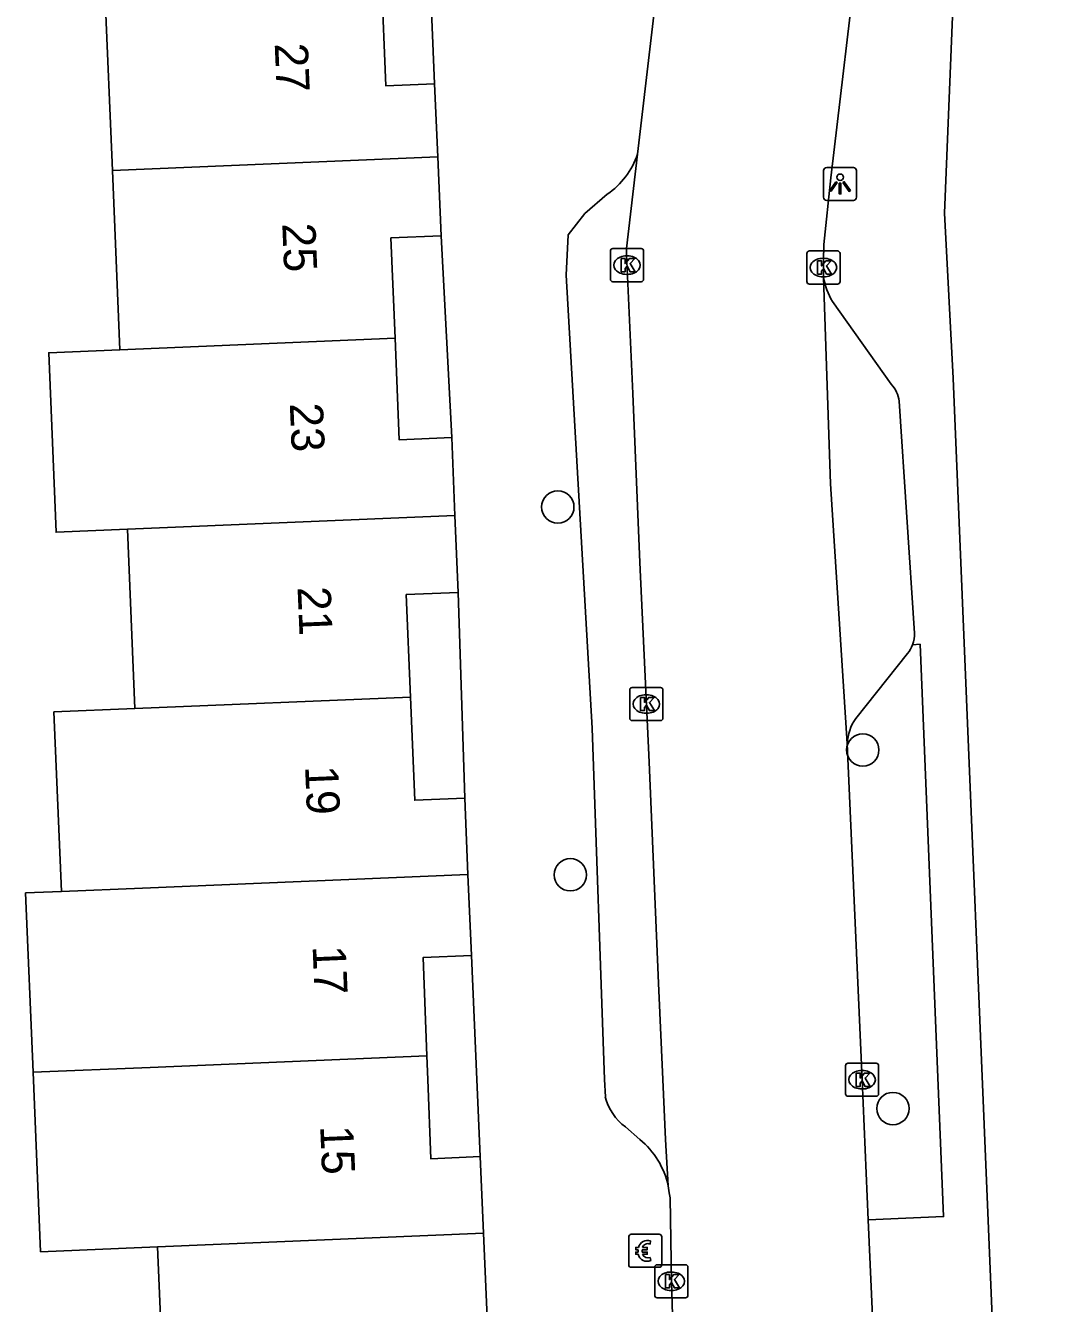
# Model space of a CAD drawing. Extents: x 161243 to 161752, y 384138 to 384885.
# Drawn here: x 161353.86 to 161384.53, y 384243.24 to 384281.86 of the extents above; entities that cross this region are included whole.
import ezdxf

# ---------------------------------------------------------------- set-up
doc = ezdxf.new("R2010")
doc.units = 0
for name, color, linetype in [('IMGEO_Betaalautomaat', 7, 'Continuous'), ('IMGEO_Boom', 7, 'Continuous'), ('IMGEO_Kolk', 7, 'Continuous'), ('IMGEO_Lichtpunt', 7, 'Continuous'), ('IMGEO_Pand', 7, 'Continuous'), ('IMGEO_Pand_nummerreeks', 7, 'Continuous'), ('IMGEO_Parkeervlak_open', 7, 'Continuous'), ('IMGEO_Rijbaan_lokaal_open', 7, 'Continuous'), ('IMGEO_Voetpad_open', 7, 'Continuous')]:
    doc.layers.add(name, color=color, linetype=linetype)

msp = doc.modelspace()

# ---------------------------------------------------------------- linework, layer by layer
at = {"layer": 'IMGEO_Betaalautomaat'}
for p, q in [((161372.086, 384244.402), (161372.086, 384245.243)), ((161372.086, 384245.243), (161372.086, 384244.402)), ((161372.161, 384245.326), (161373.002, 384245.326)), ((161373.002, 384245.326), (161372.161, 384245.326)), ((161372.748, 384245.131), (161372.731, 384245.031)), ((161373.085, 384245.252), (161373.085, 384244.411)), ((161373.085, 384244.411), (161373.085, 384245.252)), ((161372.369, 384244.79), (161372.369, 384244.858)), ((161372.49, 384244.858), (161372.49, 384244.79)), ((161372.735, 384244.625), (161372.757, 384244.538)), ((161373.011, 384244.327), (161372.17, 384244.327)), ((161372.17, 384244.327), (161373.011, 384244.327))]:
    msp.add_line(p, q, dxfattribs=at)
for points in [[(161372.369, 384244.858), (161372.3, 384244.858), (161372.3, 384244.927), (161372.379, 384244.927)], [(161372.374, 384244.721), (161372.3, 384244.721), (161372.3, 384244.79), (161372.369, 384244.79)], [(161372.501, 384244.927), (161372.648, 384244.927), (161372.648, 384244.858), (161372.49, 384244.858)], [(161372.49, 384244.79), (161372.648, 384244.79), (161372.648, 384244.721), (161372.504, 384244.721)]]:
    msp.add_lwpolyline(points, dxfattribs=at)
for centre, radius, start, end in [((161372.164, 384245.249), 0.0779, 92.4484, 184.2845), ((161372.164, 384245.249), 0.0779, 92.4484, 184.2845), ((161372.662, 384244.851), 0.293, 73.014, 165.0139), ((161372.668, 384244.864), 0.179, 69.3236, 159.5683), ((161373.008, 384245.249), 0.0779, 2.4484, 94.2845), ((161373.008, 384245.249), 0.0779, 2.4484, 94.2845), ((161372.635, 384244.776), 0.267, 191.8096, 297.0389), ((161372.668, 384244.791), 0.179, 202.7625, 291.8693), ((161372.164, 384244.405), 0.0779, 182.4484, 274.2845), ((161372.164, 384244.405), 0.0779, 182.4484, 274.2845), ((161373.008, 384244.405), 0.0779, 272.4484, 4.2845), ((161373.008, 384244.405), 0.0779, 272.4484, 4.2845)]:
    msp.add_arc(centre, radius, start, end, dxfattribs=at)
at = {"layer": 'IMGEO_Boom'}
for centre in [(161369.944, 384267.31), (161379.159, 384259.965), (161370.322, 384256.192), (161380.07, 384249.126)]:
    msp.add_circle(centre, 0.489, dxfattribs=at)
at = {"layer": 'IMGEO_Kolk'}
for p, q in [((161371.609, 384275.121), (161372.461, 384275.121)), ((161371.534, 384274.195), (161371.534, 384275.047)), ((161372.022, 384274.901), (161372.047, 384274.901)), ((161372.535, 384275.047), (161372.535, 384274.195)), ((161377.47, 384274.122), (161377.47, 384274.974)), ((161377.545, 384275.048), (161378.397, 384275.048)), ((161377.958, 384274.828), (161377.983, 384274.828)), ((161378.471, 384274.974), (161378.471, 384274.122)), ((161372.045, 384274.341), (161372.02, 384274.341)), ((161372.461, 384274.121), (161371.609, 384274.121)), ((161378.397, 384274.048), (161377.545, 384274.048)), ((161377.981, 384274.268), (161377.956, 384274.268)), ((161372.118, 384260.928), (161372.118, 384261.78)), ((161372.193, 384261.854), (161373.045, 384261.854)), ((161372.606, 384261.634), (161372.631, 384261.634)), ((161373.119, 384261.78), (161373.119, 384260.928)), ((161373.045, 384260.854), (161372.193, 384260.854)), ((161372.629, 384261.074), (161372.604, 384261.074)), ((161378.636, 384249.572), (161378.636, 384250.424)), ((161378.711, 384250.498), (161379.563, 384250.498)), ((161379.637, 384250.424), (161379.637, 384249.572)), ((161379.124, 384250.278), (161379.149, 384250.278)), ((161379.147, 384249.718), (161379.122, 384249.718)), ((161379.563, 384249.498), (161378.711, 384249.498)), ((161372.873, 384243.48), (161372.873, 384244.332)), ((161372.948, 384244.406), (161373.8, 384244.406)), ((161373.361, 384244.186), (161373.386, 384244.186)), ((161373.874, 384244.332), (161373.874, 384243.48)), ((161373.8, 384243.406), (161372.948, 384243.406)), ((161373.384, 384243.626), (161373.359, 384243.626))]:
    msp.add_line(p, q, dxfattribs=at)
for points in [[(161371.609, 384275.121), (161372.461, 384275.121)], [(161371.534, 384274.195), (161371.534, 384275.047)], [(161371.855, 384274.821), (161371.978, 384274.821), (161371.978, 384274.67), (161372.108, 384274.821), (161372.272, 384274.821), (161372.126, 384274.67), (161372.279, 384274.421), (161372.127, 384274.421), (161372.042, 384274.585), (161371.978, 384274.518), (161371.978, 384274.421), (161371.855, 384274.421), (161371.855, 384274.821)], [(161372.535, 384275.047), (161372.535, 384274.195)], [(161377.47, 384274.122), (161377.47, 384274.974)], [(161377.545, 384275.048), (161378.397, 384275.048)], [(161377.791, 384274.748), (161377.914, 384274.748), (161377.914, 384274.597), (161378.044, 384274.748), (161378.208, 384274.748), (161378.062, 384274.597), (161378.215, 384274.348), (161378.063, 384274.348), (161377.978, 384274.512), (161377.914, 384274.445), (161377.914, 384274.348), (161377.791, 384274.348), (161377.791, 384274.748)], [(161378.471, 384274.974), (161378.471, 384274.122)], [(161372.461, 384274.121), (161371.609, 384274.121)], [(161378.397, 384274.048), (161377.545, 384274.048)], [(161372.118, 384260.928), (161372.118, 384261.78)], [(161372.193, 384261.854), (161373.045, 384261.854)], [(161373.119, 384261.78), (161373.119, 384260.928)], [(161372.439, 384261.554), (161372.562, 384261.554), (161372.562, 384261.403), (161372.692, 384261.554), (161372.856, 384261.554), (161372.71, 384261.403), (161372.863, 384261.154), (161372.711, 384261.154), (161372.626, 384261.318), (161372.562, 384261.251), (161372.562, 384261.154), (161372.439, 384261.154), (161372.439, 384261.554)], [(161373.045, 384260.854), (161372.193, 384260.854)], [(161378.636, 384249.572), (161378.636, 384250.424)], [(161378.711, 384250.498), (161379.563, 384250.498)], [(161379.637, 384250.424), (161379.637, 384249.572)], [(161378.957, 384250.198), (161379.08, 384250.198), (161379.08, 384250.047), (161379.21, 384250.198), (161379.374, 384250.198), (161379.228, 384250.047), (161379.381, 384249.798), (161379.229, 384249.798), (161379.144, 384249.962), (161379.08, 384249.895), (161379.08, 384249.798), (161378.957, 384249.798), (161378.957, 384250.198)], [(161379.563, 384249.498), (161378.711, 384249.498)], [(161372.873, 384243.48), (161372.873, 384244.332)], [(161372.948, 384244.406), (161373.8, 384244.406)], [(161373.874, 384244.332), (161373.874, 384243.48)], [(161373.194, 384244.106), (161373.317, 384244.106), (161373.317, 384243.955), (161373.447, 384244.106), (161373.611, 384244.106), (161373.465, 384243.955), (161373.618, 384243.706), (161373.466, 384243.706), (161373.381, 384243.87), (161373.317, 384243.803), (161373.317, 384243.706), (161373.194, 384243.706), (161373.194, 384244.106)], [(161373.8, 384243.406), (161372.948, 384243.406)]]:
    msp.add_lwpolyline(points, dxfattribs=at)
for centre, start, end in [((161371.611, 384275.045), 91.552, 178.448), ((161371.611, 384275.045), 91.552, 178.448), ((161372.459, 384275.045), 1.552, 88.448), ((161372.459, 384275.045), 1.552, 88.448), ((161377.547, 384274.972), 91.552, 178.448), ((161377.547, 384274.972), 91.552, 178.448), ((161378.395, 384274.972), 1.552, 88.448), ((161378.395, 384274.972), 1.552, 88.448), ((161371.611, 384274.197), 181.552, 268.448), ((161371.611, 384274.197), 181.552, 268.448), ((161372.459, 384274.197), 271.552, 358.448), ((161372.459, 384274.197), 271.552, 358.448), ((161377.547, 384274.124), 181.552, 268.448), ((161377.547, 384274.124), 181.552, 268.448), ((161378.395, 384274.124), 271.552, 358.448), ((161378.395, 384274.124), 271.552, 358.448), ((161372.195, 384261.778), 91.552, 178.448), ((161372.195, 384261.778), 91.552, 178.448), ((161373.043, 384261.778), 1.552, 88.448), ((161373.043, 384261.778), 1.552, 88.448), ((161372.195, 384260.93), 181.552, 268.448), ((161372.195, 384260.93), 181.552, 268.448), ((161373.043, 384260.93), 271.552, 358.448), ((161373.043, 384260.93), 271.552, 358.448), ((161378.713, 384250.422), 91.552, 178.448), ((161378.713, 384250.422), 91.552, 178.448), ((161379.561, 384250.422), 1.552, 88.448), ((161379.561, 384250.422), 1.552, 88.448), ((161378.713, 384249.574), 181.552, 268.448), ((161378.713, 384249.574), 181.552, 268.448), ((161379.561, 384249.574), 271.552, 358.448), ((161379.561, 384249.574), 271.552, 358.448), ((161372.95, 384244.33), 91.552, 178.448), ((161372.95, 384244.33), 91.552, 178.448), ((161373.798, 384244.33), 1.552, 88.448), ((161373.798, 384244.33), 1.552, 88.448), ((161372.95, 384243.482), 181.552, 268.448), ((161372.95, 384243.482), 181.552, 268.448), ((161373.798, 384243.482), 271.552, 358.448), ((161373.798, 384243.482), 271.552, 358.448)]:
    msp.add_arc(centre, 0.0765, start, end, dxfattribs=at)
for centre, major_axis, ratio, start_param, end_param in [((161372.021, 384274.621), (-0.387, 0.002), 0.722429, 4.712389, 7.853982), ((161372.046, 384274.621), (-0.39, 0.002), 0.717154, 1.570796, 4.712389), ((161377.957, 384274.548), (-0.387, 0.002), 0.722429, 4.712389, 7.853982), ((161377.982, 384274.548), (-0.39, 0.002), 0.717154, 1.570796, 4.712389), ((161372.605, 384261.354), (-0.387, 0.002), 0.722429, 4.712389, 7.853982), ((161372.63, 384261.354), (-0.39, 0.002), 0.717154, 1.570796, 4.712389), ((161379.123, 384249.998), (-0.387, 0.002), 0.722429, 4.712389, 7.853982), ((161379.148, 384249.998), (-0.39, 0.002), 0.717154, 1.570796, 4.712389), ((161373.36, 384243.906), (-0.387, 0.002), 0.722429, 4.712389, 7.853982), ((161373.385, 384243.906), (-0.39, 0.002), 0.717154, 1.570796, 4.712389)]:
    msp.add_ellipse(centre, major_axis=major_axis, ratio=ratio, start_param=start_param, end_param=end_param, dxfattribs=at)
at = {"layer": 'IMGEO_Lichtpunt'}
for p, q in [((161377.974, 384277.478), (161377.974, 384276.671)), ((161377.974, 384277.478), (161377.974, 384276.671)), ((161378.876, 384277.573), (161378.068, 384277.573)), ((161378.876, 384277.573), (161378.068, 384277.573)), ((161378.97, 384276.671), (161378.97, 384277.478)), ((161378.97, 384276.671), (161378.97, 384277.478)), ((161378.068, 384276.577), (161378.876, 384276.577)), ((161378.068, 384276.577), (161378.876, 384276.577))]:
    msp.add_line(p, q, dxfattribs=at)
for points in [[(161378.348, 384277.142), (161378.387, 384277.114), (161378.199, 384276.852), (161378.161, 384276.879), (161378.348, 384277.142)], [(161378.45, 384277.094), (161378.497, 384277.094), (161378.497, 384276.772), (161378.45, 384276.772), (161378.45, 384277.094)], [(161378.56, 384277.114), (161378.598, 384277.141), (161378.785, 384276.879), (161378.746, 384276.851), (161378.56, 384277.114)]]:
    msp.add_lwpolyline(points, dxfattribs=at)
msp.add_circle((161378.473, 384277.276), 0.0994, dxfattribs=at)
for centre, start, end in [((161378.068, 384277.478), 90, 180), ((161378.068, 384277.478), 90, 180), ((161378.876, 384277.478), 0, 90), ((161378.876, 384277.478), 0, 90), ((161378.068, 384276.671), 180, 270), ((161378.068, 384276.671), 180, 270), ((161378.876, 384276.671), 270, 0), ((161378.876, 384276.671), 270, 360)]:
    msp.add_arc(centre, 0.0946, start, end, dxfattribs=at)
at = {"layer": 'IMGEO_Pand'}
for points in [[(161366.223, 384280.106), (161364.747, 384280.045), (161364.613, 384283.257)], [(161356.488, 384277.486), (161356.262, 384282.909)], [(161366.223, 384280.106), (161366.315, 384277.896)], [(161356.488, 384277.486), (161366.315, 384277.896)], [(161366.315, 384277.896), (161366.415, 384275.508)], [(161356.715, 384272.063), (161356.488, 384277.486)], [(161365.026, 384272.41), (161364.9, 384275.445), (161366.415, 384275.508)], [(161365.026, 384272.41), (161356.715, 384272.063)], [(161366.737, 384269.406), (161365.154, 384269.34), (161365.026, 384272.41)], [(161356.942, 384266.639), (161354.786, 384266.549), (161354.56, 384271.973), (161356.715, 384272.063)], [(161366.737, 384269.406), (161366.835, 384267.052)], [(161356.942, 384266.639), (161366.835, 384267.052)], [(161366.835, 384267.052), (161366.932, 384264.726)], [(161357.168, 384261.216), (161356.942, 384266.639)], [(161365.492, 384261.563), (161365.363, 384264.66), (161366.932, 384264.726)], [(161365.492, 384261.563), (161357.168, 384261.216)], [(161367.134, 384258.507), (161365.622, 384258.444), (161365.492, 384261.563)], [(161354.946, 384255.691), (161354.72, 384261.114), (161357.168, 384261.216)], [(161367.134, 384258.507), (161367.23, 384256.203)], [(161367.23, 384256.203), (161357.395, 384255.793), (161354.946, 384255.691)], [(161367.23, 384256.203), (161367.332, 384253.749)], [(161354.089, 384250.222), (161353.862, 384255.646), (161354.946, 384255.691)], [(161365.989, 384250.718), (161365.875, 384253.688), (161367.332, 384253.749)], [(161354.089, 384250.222), (161357.622, 384250.369), (161365.989, 384250.718)], [(161367.599, 384247.673), (161366.107, 384247.609), (161366.016, 384250), (161365.989, 384250.718)], [(161357.848, 384244.946), (161354.315, 384244.799), (161354.089, 384250.222)], [(161367.599, 384247.673), (161367.698, 384245.357)], [(161357.848, 384244.946), (161367.698, 384245.357)], [(161367.698, 384245.357), (161367.806, 384242.815)], [(161358.075, 384239.523), (161357.848, 384244.946)]]:
    msp.add_lwpolyline(points, dxfattribs=at)
at = {"layer": 'IMGEO_Parkeervlak_open'}
msp.add_lwpolyline([(161380.509, 384262.883), (161378.945, 384260.915)], dxfattribs=at)
for centre, radius, start, end in [((161379.797, 384263.474), 0.925, 320.3061, 339.3694), ((161380.05, 384260.123), 1.359, 144.3632, 178.3103)]:
    msp.add_arc(centre, radius, start, end, dxfattribs=at)
at = {"layer": 'IMGEO_Rijbaan_lokaal_open'}
for points in [[(161372.354, 384277.971), (161373.201, 384285.193)], [(161379.046, 384284.508), (161378.196, 384277.255), (161377.986, 384275.243), (161377.967, 384274.752), (161377.968, 384274.518), (161377.976, 384274.251)], [(161373.282, 384246.79), (161373.201, 384248.193), (161373.121, 384250), (161372.991, 384252.917), (161372.701, 384259.592), (161372.422, 384265.637), (161372.209, 384270.741), (161372.023, 384274.955), (161372.021, 384275.127), (161372.354, 384277.971)], [(161377.976, 384274.251), (161378.187, 384268.009), (161378.691, 384260.163)], [(161378.691, 384260.163), (161379.137, 384249.998), (161379.324, 384245.758)], [(161373.499, 384239.768), (161373.501, 384239.874), (161373.376, 384243.89), (161373.336, 384246.428), (161373.313, 384246.58), (161373.282, 384246.79)], [(161379.324, 384245.758), (161379.483, 384242.162)]]:
    msp.add_lwpolyline(points, dxfattribs=at)
at = {"layer": 'IMGEO_Voetpad_open'}
for points in [[(161385.58, 384183.057), (161384.168, 384216.383), (161381.889, 384271.203), (161381.629, 384276.193), (161382.268, 384292.057), (161382.629, 384295.041)], [(161365.967, 384286.221), (161366.223, 384280.106)], [(161371.38, 384249.483), (161371.358, 384250), (161370.987, 384260.621), (161370.196, 384274.318), (161370.254, 384275.533), (161370.761, 384276.181), (161371.436, 384276.761)], [(161366.415, 384275.508), (161366.737, 384269.406)], [(161380.018, 384271.022), (161378.241, 384273.518)], [(161380.719, 384263.501), (161380.254, 384270.509)], [(161366.932, 384264.726), (161367.134, 384258.507)], [(161379.324, 384245.758), (161381.602, 384245.859), (161380.892, 384263.162), (161380.663, 384263.148)], [(161367.332, 384253.749), (161367.497, 384250), (161367.599, 384247.673)], [(161372.423, 384248.19), (161371.991, 384248.57)]]:
    msp.add_lwpolyline(points, dxfattribs=at)
for centre, radius, start, end in [((161370.038, 384278.775), 2.451, 304.7656, 340.8609), ((161380.238, 384274.654), 2.298, 190.1116, 209.6411), ((161379.375, 384270.415), 0.884, 6.0763, 43.3322), ((161379.832, 384263.461), 0.888, 339.3749, 2.5965), ((161372.942, 384249.868), 1.609, 193.8316, 233.7511), ((161370.804, 384246.233), 2.54, 12.6681, 50.396)]:
    msp.add_arc(centre, radius, start, end, dxfattribs=at)

# ---------------------------------------------------------------- texts
at = {"layer": 'IMGEO_Pand_nummerreeks'}
for s, rotation, p in [('27', 272.4061, (161361.389, 384281.316)), ('25', 272.4061, (161361.617, 384275.878)), ('23', 272.4062, (161361.845, 384270.44)), ('21', 272.4061, (161362.079, 384264.889)), ('19', 272.4062, (161362.306, 384259.473)), ('17', 272.4062, (161362.534, 384254.035)), ('15', 272.4062, (161362.763, 384248.597))]:
    msp.add_text(s, height=1, rotation=rotation, dxfattribs=at).set_placement(p)

doc.saveas('drawing.dxf')
